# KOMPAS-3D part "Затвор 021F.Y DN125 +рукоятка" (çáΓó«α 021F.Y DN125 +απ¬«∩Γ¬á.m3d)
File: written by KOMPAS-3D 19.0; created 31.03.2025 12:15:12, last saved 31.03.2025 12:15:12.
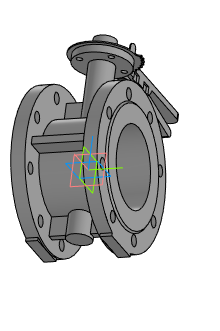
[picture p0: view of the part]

Document properties: Автор: Евгений; Полное имя файла: Затвор 021F.Y DN125 +рукоятка.a3d

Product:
- Part/product: Затвор 021F.Y DN125 +рукоятка
    Масса: 28.6092

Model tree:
1. Операция без истории:1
